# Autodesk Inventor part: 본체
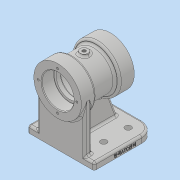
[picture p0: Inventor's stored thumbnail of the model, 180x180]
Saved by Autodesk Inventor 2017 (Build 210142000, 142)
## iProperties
Part Number: 본체
Material: 일반
Document SubType Name: Modeling
Designer: mrc
Density: 1 g/cm^3
Appearance: 기본값
Author: mrc
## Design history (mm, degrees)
sketch "스케치2"
  geometry: L1 (0, 35)-(-22, 35); L2 (-22, 35)-(-22, 28.5); L3 (-22, 28.5)-(-56, 28.5); L4 (-56, 28.5)-(-56, 35); L5 (-56, 35)-(-78, 35); L6 (-78, 35)-(-78, 23.5); L7 (-78, 23.5)-(-60, 23.5); L8 (-60, 23.5)-(-60, 20); L9 (-60, 20)-(-54, 20); L10 (-54, 20)-(-54, 23); L11 (-54, 23)-(-24, 23); L12 (-24, 23)-(-24, 20); L13 (-24, 20)-(-18, 20); L14 (-18, 20)-(-18, 23.5); L15 (-18, 23.5)-(0, 23.5); L16 (0, 35)-(0, 23.5); L17 (0, 0)-(-45.758, 0)
  constraints: 34 end point, 10 perpendicular, 4 horizontal, 2 point on line, 2 vertical, 1 vertical alignment
  dimensions: "d3" = 47 diameter of L15 L17; "d4" = 40 diameter of L13 L17; "d5" = 46 diameter of L11 L17; "d6" = 40 diameter of L9 L17; "d7" = 47 diameter of L7 L17; "d8" = 70 diameter of L1 L17; "d9" = 57 diameter of L3 L17; "d11" = 18 distance of L14.end L15.end; "d12" = 6 distance of L12.end L13.end; "d13" = 18 distance of L6.end L7.end; "d14" = 6 distance of L8.end L9.end; "d15" = 30 distance of L10.end L11.end; "d16" = 22 distance of L1.start L1.end; "d17" = 22 distance of L4.end L5.end
revolve "회전1" sketch "스케치2" stored, may be unused: angle "d18" = 90 deg
sketch "스케치3" dims "d19" = 57
  geometry: 3 further points
  constraints: 2 vertical alignment, 1 coincident, 2 other
hole "구멍1" sketch "스케치3" at (0, 28.5) diameter "d20" = 3.242; stored, may be unused: countersink angle "d24" = 90 deg, drill point angle "d26" = 118 deg; dims "d21" = 10, "d22" = 4, "d23" = 2, "d25" = 12
node "작업 평면2"
sketch "스케치4"
  geometry: L1 (0, -35)-(0, 35) reference; C1 r 6 at (-39, 0); 2 further points
  constraints: 1 centre point, 1 horizontal alignment, 1 midpoint
  dimensions: "d32" = 12 diameter of C1; "d33" = 39 distance from line of C1.centre L1
extrude "돌출2" join sketch "스케치4" stored distance "d34" = 20; taper "d35" = 0 deg
hole "구멍2" diameter "d38" = 5.188; stored, may be unused: countersink angle "d42" = 90 deg, drill point angle "d44" = 0 deg; dims "d36" = 10, "d37" = 10, "d39" = 12, "d40" = 4, "d41" = 2, "d43" = 16
node "작업 평면3"
sketch "스케치5"
  geometry: L1 (5, -49)-(95, -49); L2 (95, -49)-(95, 49); L3 (95, 49)-(5, 49); L4 (5, -49)-(5, 49); L5 (0, 35)-(0, -35) reference; 2 further points
  constraints: 8 end point, 2 perpendicular, 1 coincident, 1 horizontal, 1 parallel
  dimensions: "d47" = 98 distance of L1.end L2.end; "d83" = 49 distance from line of point (0, 0) L1; "d84" = 90 distance of L1.start L1.end; "d85" = 5 distance between parallel lines of L5 L4
extrude "돌출3" join sketch "스케치5" distance "d48" = 10; taper "d49" = 0 deg
fillet "모깎기1" dims "d50" = 20
node "작업 평면4"
sketch "스케치6"
  geometry: L1 (0, 35)-(72, 35); L2 (72, 35)-(72, -35); L3 (72, -35)-(0, -35); C1 r 35 at (0, 0) reference; A1 r 35 centre (0, 0) between (0, 35) and (0, -35) reference; A2 r 35 centre (0, 0) between (0, -35) and (0, 35); 1 further point
  constraints: 6 end point, 4 point on circle, 2 horizontal, 2 tangent, 1 centre point, 1 coincident, 1 vertical
  dimensions: "d52" = 72 distance from line of L2 point (0, 0)
extrude "돌출6" join sketch "스케치6" distance "d74" = 10; taper "d75" = 0 deg
sketch "스케치7"
  geometry: L1 (-71.927, -39.577)-(-83, -70); L2 (-95, -70)-(-75, -70) reference; L3 (-75, -70)-(-5, -70) reference; 1 further point
  constraints: 2 end point, 1 point on line
  dimensions: "d55" = 70 deg angle of L3 L1; "d56" = 12 distance of L2.start L1.end
feature "리브1" sketch "스케치7" dims "d57" = 1, "d58" = 10, "d59" = 0, "d60" = 0, "d61" = 1, "d62" = 1
sketch "스케치8"
  geometry: L1 (-5, -49)-(-5, 49) reference; C1 r 4.5 at (-39, -29); C2 r 4.5 at (-75, -29); C3 r 4.5 at (-39, 29); C4 r 4.5 at (-75, 29); 1 further point
  constraints: 4 centre point, 2 vertical alignment, 1 horizontal alignment
  dimensions: "d63" = 9 diameter of C1; "d64" = 9 diameter of C2; "d65" = 36 distance of C2.centre C1.centre; "d67" = 9 diameter of C3; "d68" = 9 diameter of C4; "d69" = 36 distance of C4.centre C3.centre; "d70" = 58 distance of C4.centre C2.centre; "d71" = 29 vertical distance of C1.centre point (0, 0); "d86" = 70 distance from line of C2.centre L1
extrude "돌출5" cut sketch "스케치8" distance "d72" = 10; taper "d73" = 0 deg
fillet "모깎기2" dims "d76" = 0.3, "d77" = 3
chamfer "모따기1" distance "d78" = 1; stored, may be unused: second distance "d79" = 2, angle "d80" = 45 deg
fillet "모깎기3" dims "d81" = 3
fillet "모깎기5" dims "d87" = 3
fillet "모깎기6" dims "d88" = 3
sketch "스케치9"
  geometry: L1 (0, 0)-(67, 0) reference; L2 (-3, 7)-(-3, 0) reference; 2 further points
  constraints: 1 other
  dimensions: "d89" = 4 distance from line of L1 point (42, 4); "d90" = 45 distance from line of point (42, 4) L2
feature "엠보싱1" sketch "스케치9" dims "d3" = 47, "d4" = 40, "d5" = 46, "d6" = 40, "d7" = 47, "d8" = 70, "d9" = 57, "d11" = 18, "d12" = 6, "d13" = 18, "d14" = 6, "d15" = 30, "d16" = 22, "d17" = 22, "d91" = 0.5, "d92" = 0
node "솔리드2"
pattern_circular "원형 패턴1" dims angle "d28" = 360 deg
other parameters: "d31" = 31.5, "d51" = -5
